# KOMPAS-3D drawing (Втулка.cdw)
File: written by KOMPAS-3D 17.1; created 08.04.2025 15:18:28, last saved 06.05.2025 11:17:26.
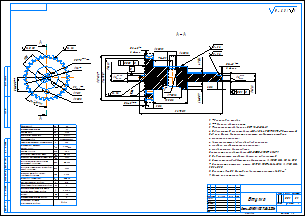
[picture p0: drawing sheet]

Sheet 1: A2, landscape

Title block, sheet 1: name: Втулка; material: Сталь 40ХН2МА ГОСТ 4543-2016; mass: 0,01; sheets: 1; sheet format: A2; stored path: C:\Users\DymLe\Documents\Рабочая папка\чертежи\3В86\чертежи для Вани\ЕИЛЮ.722622.001.cdw
Table, sheet 1:
  1208827137

Views: Вид 1, Спереди, Вид сопряженного червяка, Разрез А-А
Referenced files in C:\Users\DymLe\Documents\Рабочая папка\чертежи\3В86\чертежи для Вани\: ЕИЛЮ.722622.001.m3d
Referenced files in D:\документация\Индюшка\РКД 3В86\: ЕИЛЮ.722622.001.m3d
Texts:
  Ячейка таблицы
  Ra 0,80
  Ra 3,2
  ЕИЛЮ.722622.001
  Обозначение чертежа
  сопряженного червяка
  Делительный диаметр червяка
  Модуль
  Максимальный делительный угол
  подъема линии витка червяка
  Число витков сопряженного червяка
  Межосевое расстояние
  Допуск на торцовое биение
  базовой поверхности
  Предельные отклонения межосевого
  угла в обработке
  Предельные смещения средней
  плоскости в обработке
  Допуск на погрешность профиля зуба
  Предельное отклонение шага
  Высота до хорды
  Делительная толщина
  зуба по хорде
  Степень точности по ГОСТ 16502-83
  Исходный червяк
  Направление линии зуба
  Высота зуба
  Делительный диаметр
  Число зубьев
  Червяк
  f xc2
  f Pt2
  GAU
  ГОСТ 24438-80
  правое
  Ra 1,6
  * Размеры для справок.
  ** Размеры обеспеч. инстр.
  Технические требования по ОСТ 92-0400-69.
  Поверхность Б покрыть бронзой БрАЖ9-4 ГОСТ 18175-78 толщиной
  5-9 мкм. Бронзу допускается наносить следующими методами:
  ‑ плазменное напыление;
  - высокоскоростное (сверхзвуковое) напыление;
  - холодное газодинамическое напыление;
  - гальвоническое бронзирование.
  Допускается покрывать бронзой БрОФ10-1 ГОСТ 613-79.
  Не допускается попадание бронзы на поверхгость В.
  Деталь термообрабботать с обеспечением  в 1000 МПа, 30..34 HRC.
  Допускается материал:  сталь 30ХГСА ГОСТ 4543-2016,  в 950 МПа,
  30...34 HRC.
  Покрытие Хим.Н3. Площадь поверхности покрытия 14,01 см 2 .
  Массу не контролировать.
  Ra 6,3
  Ra 6,3 ( )
  gliv
  BOSimple***Material:fd48d8f1-45f7-47f0-a9f1-b1ec4985fdbe
Dimensions and other numbers on the sheet: 1; 9; 5; 5,5±0,05; 1,5; 0,75; 3; 16; 4; 0,5; 7 10'48"; 10 0,03; 0,004; 0,071; 0,018; 0,46; 0,845 -0,12; 7-B; 0,975; 32; 32,75; 2; 2 фаски; 0,2; 0,3; 14,95; 17,821; 1,3±0,07; 13,5; 2,5; 3,5; 7,5±0,1; 6,7; 0,01; 0,005; 5:1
